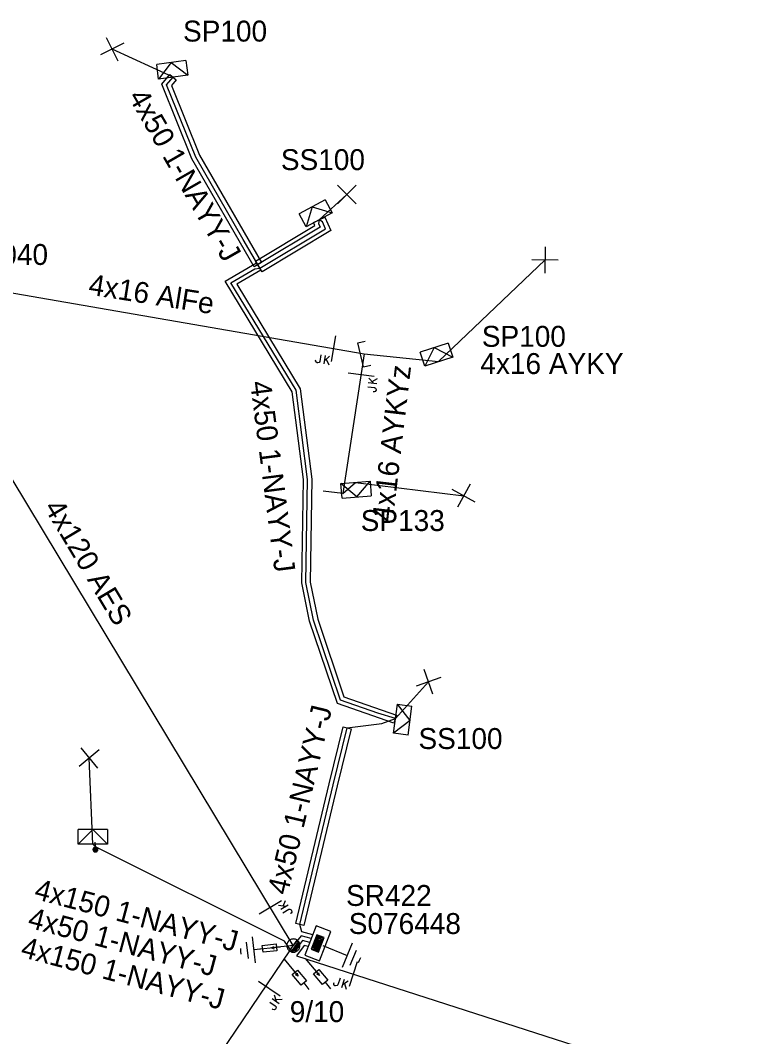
# Model space of a CAD drawing. Extents: x -788458 to -786145, y -1154772 to -1152372.
# Drawn here: x -786394.96 to -786360.56, y -1153494.9 to -1153446.32 of the extents above; entities that cross this region are included whole.
import ezdxf

# ---------------------------------------------------------------- set-up
doc = ezdxf.new("R2010")
doc.units = 0
for name, color, linetype in [('Vrstva 1', 7, 'Continuous'), ('Vrstva 12', 7, 'Continuous'), ('Vrstva 13', 7, 'Continuous'), ('Vrstva 14', 7, 'Continuous'), ('Vrstva 15', 7, 'Continuous'), ('Vrstva 16', 7, 'Continuous'), ('Vrstva 18', 7, 'Continuous'), ('Vrstva 2', 7, 'Continuous'), ('Vrstva 20', 7, 'Continuous'), ('Vrstva 28', 7, 'Continuous'), ('Vrstva 29', 7, 'Continuous'), ('Vrstva 30', 7, 'Continuous'), ('Vrstva 31', 7, 'Continuous'), ('Vrstva 33', 7, 'Continuous'), ('Vrstva 34', 7, 'Continuous'), ('Vrstva 5', 7, 'Continuous'), ('Vrstva 50', 7, 'Continuous'), ('Vrstva 51', 7, 'Continuous'), ('Vrstva 52', 7, 'Continuous'), ('Vrstva 54', 7, 'Continuous'), ('Vrstva 55', 7, 'Continuous'), ('Vrstva 59', 7, 'Continuous'), ('Vrstva 6', 7, 'Continuous'), ('Vrstva 8', 7, 'Continuous'), ('Vrstva 9', 7, 'Continuous')]:
    doc.layers.add(name, color=color, linetype=linetype)

# ---------------------------------------------------------------- blocks, each defined once
blk = doc.blocks.new('NN440')
at = {"layer": 'Vrstva 2'}
for points in [[(0.631, -0.004), (0.627, 0.062), (0.617, 0.127), (0.6, 0.191), (0.577, 0.252), (0.547, 0.311), (0.511, 0.366), (0.469, 0.417), (0.423, 0.464), (0.371, 0.505), (0.316, 0.542), (0.257, 0.571), (0.196, 0.595), (0.132, 0.612), (0.067, 0.622), (0.001, 0.626), (-0.065, 0.622), (-0.13, 0.612), (-0.194, 0.595), (-0.255, 0.571), (-0.314, 0.542), (-0.369, 0.505), (-0.42, 0.464), (-0.467, 0.417), (-0.509, 0.366), (-0.544, 0.311), (-0.574, 0.252), (-0.598, 0.191), (-0.615, 0.127), (-0.626, 0.062), (-0.629, -0.004), (-0.626, -0.07), (-0.615, -0.135), (-0.598, -0.199), (-0.574, -0.26), (-0.544, -0.319), (-0.509, -0.374), (-0.467, -0.426), (-0.42, -0.472), (-0.369, -0.514), (-0.314, -0.55), (-0.255, -0.58), (-0.194, -0.603), (-0.13, -0.62), (-0.065, -0.631), (0.001, -0.634), (0.067, -0.631), (0.132, -0.62), (0.196, -0.603), (0.257, -0.58), (0.316, -0.55), (0.371, -0.514), (0.423, -0.472), (0.469, -0.426), (0.511, -0.374), (0.547, -0.319), (0.577, -0.26), (0.6, -0.199), (0.617, -0.135), (0.627, -0.07), (0.631, -0.004)], [(-0.631, 0), (0.629, 0)], [(-0.601, -0.177), (0.57, -0.177)], [(-0.513, -0.325), (0.501, -0.325)], [(-0.375, -0.473), (0.353, -0.473)]]:
    blk.add_lwpolyline(points, dxfattribs=at)
blk = doc.blocks.new('NN840')
at = {"layer": 'Vrstva 15'}
for points in [[(0.003, 0.619), (0.003, -0.631)], [(-0.538, -0.385), (-0.538, -0.71)], [(-0.332, -0.385), (-0.332, -0.798)], [(-0.332, -0.641), (-0.125, -0.385)], [(-0.745, -0.71), (-0.745, -0.66)], [(-0.73, -0.764), (-0.745, -0.71)], [(-0.657, -0.798), (-0.73, -0.764)], [(-0.627, -0.798), (-0.657, -0.798)], [(-0.558, -0.764), (-0.627, -0.798)], [(-0.538, -0.71), (-0.558, -0.764)], [(-0.263, -0.557), (-0.091, -0.798)]]:
    blk.add_lwpolyline(points, dxfattribs=at)
blk = doc.blocks.new('NN800')
at = {"layer": 'Vrstva 1'}
for points in [[(-0.442, 0.442), (0.442, -0.442)], [(-0.442, -0.442), (0.442, 0.442)]]:
    blk.add_lwpolyline(points, dxfattribs=at)
blk = doc.blocks.new('NN820')
at = {"layer": 'Vrstva 13'}
for points in [[(-0.003, 0.004), (-0.003, -1.049)], [(-0.165, -0.813), (0.165, -0.813)], [(-0.165, -1.473), (-0.165, -0.813)], [(-0.003, -1.049), (-0.062, -0.926)], [(-0.003, -1.049), (0.057, -0.926)], [(0.165, -0.813), (0.165, -1.473)], [(0.165, -1.473), (-0.165, -1.473)], [(-0.003, -1.473), (-0.003, -1.871)]]:
    blk.add_lwpolyline(points, dxfattribs=at)
blk = doc.blocks.new('NN620')
at = {"layer": 'Vrstva 8'}
for points in [[(0.752, 0.004), (-0.748, 0.004)], [(-0.748, 0.004), (-0.748, -0.746)], [(0.752, -0.746), (0.752, 0.004)], [(0.368, -0.18), (-0.376, -0.18)], [(-0.376, -0.18), (-0.376, -0.558)], [(0.321, -0.227), (-0.329, -0.227)], [(-0.329, -0.227), (-0.329, -0.51)], [(0.274, -0.274), (-0.281, -0.274)], [(-0.281, -0.274), (-0.281, -0.463)], [(-0.281, -0.463), (0.274, -0.463)], [(0.227, -0.321), (-0.234, -0.321)], [(-0.234, -0.321), (-0.234, -0.416)], [(-0.234, -0.416), (0.227, -0.416)], [(-0.193, -0.369), (0.185, -0.369)], [(0.227, -0.416), (0.227, -0.321)], [(0.274, -0.463), (0.274, -0.274)], [(0.321, -0.51), (0.321, -0.227)], [(0.368, -0.558), (0.368, -0.18)], [(-0.748, -0.746), (0.752, -0.746)], [(-0.376, -0.558), (0.368, -0.558)], [(-0.329, -0.51), (0.321, -0.51)]]:
    blk.add_lwpolyline(points, dxfattribs=at)
blk = doc.blocks.new('NN630')
at = {"layer": 'Vrstva 9'}
for points in [[(-0.003, -0.7), (-0.703, 0)], [(-0.703, -0.7), (-0.703, 0), (0.697, 0), (0.697, -0.7)], [(-0.003, -0.7), (0.697, 0)], [(-0.703, -0.7), (0.697, -0.7)]]:
    blk.add_lwpolyline(points, dxfattribs=at)
blk = doc.blocks.new('NN810')
at = {"layer": 'Vrstva 14'}
for points in [[(0.004, -0.64), (0.004, -1.89)], [(0.629, -1.89), (-0.621, -1.89)], [(0.388, -2.2), (-0.399, -2.2)], [(0.004, -2.515), (-0.124, -2.515)], [(0.137, -2.515), (0.004, -2.515)]]:
    blk.add_lwpolyline(points, dxfattribs=at)
blk = doc.blocks.new('NN500')
at = {"layer": 'Vrstva 2'}
for points in [[(-0.001, -0.235), (0.023, -0.234), (0.048, -0.23), (0.071, -0.224), (0.094, -0.215), (0.116, -0.204), (0.137, -0.191), (0.156, -0.175), (0.173, -0.158), (0.189, -0.139), (0.202, -0.118), (0.213, -0.096), (0.222, -0.073), (0.229, -0.049), (0.232, -0.025), (0.234, 0), (0.232, 0.024), (0.229, 0.048), (0.222, 0.072), (0.213, 0.095), (0.202, 0.117), (0.189, 0.138), (0.173, 0.157), (0.156, 0.174), (0.137, 0.19), (0.116, 0.203), (0.094, 0.214), (0.071, 0.223), (0.048, 0.229), (0.023, 0.233), (-0.001, 0.235), (-0.026, 0.233), (-0.05, 0.229), (-0.074, 0.223), (-0.097, 0.214), (-0.119, 0.203), (-0.139, 0.19), (-0.158, 0.174), (-0.176, 0.157), (-0.191, 0.138), (-0.205, 0.117), (-0.216, 0.095), (-0.225, 0.072), (-0.231, 0.048), (-0.235, 0.024), (-0.236, 0), (-0.235, -0.025), (-0.231, -0.049), (-0.225, -0.073), (-0.216, -0.096), (-0.205, -0.118), (-0.191, -0.139), (-0.176, -0.158), (-0.158, -0.175), (-0.139, -0.191), (-0.119, -0.204), (-0.097, -0.215), (-0.074, -0.224), (-0.05, -0.23), (-0.026, -0.234), (-0.001, -0.235)], [(-0.001, -0.235), (0.023, -0.234), (0.048, -0.23), (0.071, -0.224), (0.094, -0.215), (0.116, -0.204), (0.137, -0.191), (0.156, -0.175), (0.173, -0.158), (0.189, -0.139), (0.202, -0.118), (0.213, -0.096), (0.222, -0.073), (0.229, -0.049), (0.232, -0.025), (0.234, 0), (0.232, 0.024), (0.229, 0.048), (0.222, 0.072), (0.213, 0.095), (0.202, 0.117), (0.189, 0.138), (0.173, 0.157), (0.156, 0.174), (0.137, 0.19), (0.116, 0.203), (0.094, 0.214), (0.071, 0.223), (0.048, 0.229), (0.023, 0.233), (-0.001, 0.235), (-0.026, 0.233), (-0.05, 0.229), (-0.074, 0.223), (-0.097, 0.214), (-0.119, 0.203), (-0.139, 0.19), (-0.158, 0.174), (-0.176, 0.157), (-0.191, 0.138), (-0.205, 0.117), (-0.216, 0.095), (-0.225, 0.072), (-0.231, 0.048), (-0.235, 0.024), (-0.236, 0), (-0.235, -0.025), (-0.231, -0.049), (-0.225, -0.073), (-0.216, -0.096), (-0.205, -0.118), (-0.191, -0.139), (-0.176, -0.158), (-0.158, -0.175), (-0.139, -0.191), (-0.119, -0.204), (-0.097, -0.215), (-0.074, -0.224), (-0.05, -0.23), (-0.026, -0.234), (-0.001, -0.235)], [(-0.001, -0.206), (0.02, -0.205), (0.041, -0.201), (0.062, -0.196), (0.082, -0.188), (0.101, -0.178), (0.12, -0.167), (0.136, -0.153), (0.151, -0.138), (0.165, -0.121), (0.177, -0.103), (0.186, -0.084), (0.194, -0.064), (0.2, -0.043), (0.203, -0.022), (0.204, 0), (0.203, 0.021), (0.2, 0.042), (0.194, 0.063), (0.186, 0.083), (0.177, 0.102), (0.165, 0.12), (0.151, 0.137), (0.136, 0.152), (0.12, 0.166), (0.101, 0.177), (0.082, 0.187), (0.062, 0.195), (0.041, 0.2), (0.02, 0.204), (-0.001, 0.205), (-0.023, 0.204), (-0.044, 0.2), (-0.065, 0.195), (-0.085, 0.187), (-0.104, 0.177), (-0.122, 0.166), (-0.139, 0.152), (-0.154, 0.137), (-0.167, 0.12), (-0.179, 0.102), (-0.189, 0.083), (-0.197, 0.063), (-0.202, 0.042), (-0.205, 0.021), (-0.207, 0), (-0.205, -0.022), (-0.202, -0.043), (-0.197, -0.064), (-0.189, -0.084), (-0.179, -0.103), (-0.167, -0.121), (-0.154, -0.138), (-0.139, -0.153), (-0.122, -0.167), (-0.104, -0.178), (-0.085, -0.188), (-0.065, -0.196), (-0.044, -0.201), (-0.023, -0.205), (-0.001, -0.206)], [(-0.001, -0.176), (0.017, -0.175), (0.035, -0.172), (0.053, -0.168), (0.07, -0.161), (0.087, -0.153), (0.102, -0.143), (0.116, -0.131), (0.129, -0.118), (0.141, -0.104), (0.151, -0.088), (0.159, -0.072), (0.166, -0.055), (0.171, -0.037), (0.174, -0.019), (0.175, 0), (0.174, 0.018), (0.171, 0.036), (0.166, 0.054), (0.159, 0.071), (0.151, 0.087), (0.141, 0.103), (0.129, 0.117), (0.116, 0.13), (0.102, 0.142), (0.087, 0.152), (0.07, 0.16), (0.053, 0.167), (0.035, 0.172), (0.017, 0.174), (-0.001, 0.175), (-0.02, 0.174), (-0.038, 0.172), (-0.056, 0.167), (-0.073, 0.16), (-0.089, 0.152), (-0.105, 0.142), (-0.119, 0.13), (-0.132, 0.117), (-0.143, 0.103), (-0.153, 0.087), (-0.162, 0.071), (-0.168, 0.054), (-0.173, 0.036), (-0.176, 0.018), (-0.177, 0), (-0.176, -0.019), (-0.173, -0.037), (-0.168, -0.055), (-0.162, -0.072), (-0.153, -0.088), (-0.143, -0.104), (-0.132, -0.118), (-0.119, -0.131), (-0.105, -0.143), (-0.089, -0.153), (-0.073, -0.161), (-0.056, -0.168), (-0.038, -0.172), (-0.02, -0.175), (-0.001, -0.176)], [(-0.001, -0.147), (0.014, -0.146), (0.029, -0.143), (0.044, -0.139), (0.058, -0.134), (0.072, -0.127), (0.085, -0.119), (0.097, -0.109), (0.107, -0.098), (0.117, -0.086), (0.125, -0.073), (0.132, -0.06), (0.138, -0.046), (0.142, -0.031), (0.144, -0.016), (0.145, 0), (0.144, 0.015), (0.142, 0.03), (0.138, 0.045), (0.132, 0.059), (0.125, 0.073), (0.117, 0.086), (0.107, 0.097), (0.097, 0.108), (0.085, 0.118), (0.072, 0.126), (0.058, 0.133), (0.044, 0.139), (0.029, 0.143), (0.014, 0.145), (-0.001, 0.146), (-0.017, 0.145), (-0.032, 0.143), (-0.046, 0.139), (-0.061, 0.133), (-0.074, 0.126), (-0.087, 0.118), (-0.099, 0.108), (-0.11, 0.097), (-0.119, 0.086), (-0.128, 0.073), (-0.135, 0.059), (-0.14, 0.045), (-0.144, 0.03), (-0.147, 0.015), (-0.147, 0), (-0.147, -0.016), (-0.144, -0.031), (-0.14, -0.046), (-0.135, -0.06), (-0.128, -0.073), (-0.119, -0.086), (-0.11, -0.098), (-0.099, -0.109), (-0.087, -0.119), (-0.074, -0.127), (-0.061, -0.134), (-0.046, -0.139), (-0.032, -0.143), (-0.017, -0.146), (-0.001, -0.147)], [(-0.001, -0.117), (0.011, -0.116), (0.023, -0.114), (0.035, -0.111), (0.046, -0.107), (0.057, -0.101), (0.067, -0.095), (0.077, -0.087), (0.085, -0.078), (0.093, -0.069), (0.1, -0.059), (0.105, -0.048), (0.11, -0.036), (0.113, -0.025), (0.115, -0.013), (0.115, 0), (0.115, 0.012), (0.113, 0.024), (0.11, 0.036), (0.105, 0.047), (0.1, 0.058), (0.093, 0.068), (0.085, 0.078), (0.077, 0.086), (0.067, 0.094), (0.057, 0.101), (0.046, 0.106), (0.035, 0.11), (0.023, 0.114), (0.011, 0.116), (-0.001, 0.116), (-0.013, 0.116), (-0.025, 0.114), (-0.037, 0.11), (-0.049, 0.106), (-0.059, 0.101), (-0.07, 0.094), (-0.079, 0.086), (-0.088, 0.078), (-0.096, 0.068), (-0.102, 0.058), (-0.108, 0.047), (-0.112, 0.036), (-0.115, 0.024), (-0.117, 0.012), (-0.118, 0), (-0.117, -0.013), (-0.115, -0.025), (-0.112, -0.036), (-0.108, -0.048), (-0.102, -0.059), (-0.096, -0.069), (-0.088, -0.078), (-0.079, -0.087), (-0.07, -0.095), (-0.059, -0.101), (-0.049, -0.107), (-0.037, -0.111), (-0.025, -0.114), (-0.013, -0.116), (-0.001, -0.117)], [(-0.001, -0.087), (0.008, -0.087), (0.017, -0.085), (0.026, -0.083), (0.034, -0.08), (0.042, -0.076), (0.05, -0.071), (0.057, -0.065), (0.063, -0.059), (0.069, -0.051), (0.074, -0.044), (0.078, -0.036), (0.081, -0.027), (0.084, -0.019), (0.085, -0.01), (0.086, 0), (0.085, 0.009), (0.084, 0.018), (0.081, 0.026), (0.078, 0.035), (0.074, 0.043), (0.069, 0.051), (0.063, 0.058), (0.057, 0.064), (0.05, 0.07), (0.042, 0.075), (0.034, 0.079), (0.026, 0.082), (0.017, 0.085), (0.008, 0.086), (-0.001, 0.087), (-0.01, 0.086), (-0.019, 0.085), (-0.028, 0.082), (-0.037, 0.079), (-0.045, 0.075), (-0.052, 0.07), (-0.059, 0.064), (-0.066, 0.058), (-0.072, 0.051), (-0.077, 0.043), (-0.081, 0.035), (-0.084, 0.026), (-0.086, 0.018), (-0.088, 0.009), (-0.088, 0), (-0.088, -0.01), (-0.086, -0.019), (-0.084, -0.027), (-0.081, -0.036), (-0.077, -0.044), (-0.072, -0.052), (-0.066, -0.059), (-0.059, -0.065), (-0.052, -0.071), (-0.045, -0.076), (-0.037, -0.08), (-0.028, -0.083), (-0.019, -0.085), (-0.01, -0.087), (-0.001, -0.087)], [(-0.001, -0.058), (0.005, -0.057), (0.011, -0.056), (0.016, -0.055), (0.022, -0.053), (0.027, -0.05), (0.032, -0.047), (0.037, -0.043), (0.041, -0.039), (0.045, -0.034), (0.048, -0.029), (0.051, -0.024), (0.053, -0.018), (0.055, -0.012), (0.056, -0.006), (0.056, 0), (0.056, 0.006), (0.055, 0.011), (0.053, 0.017), (0.051, 0.023), (0.048, 0.028), (0.045, 0.033), (0.041, 0.038), (0.037, 0.042), (0.032, 0.046), (0.027, 0.049), (0.022, 0.052), (0.016, 0.054), (0.011, 0.056), (0.005, 0.057), (-0.001, 0.057), (-0.007, 0.057), (-0.013, 0.056), (-0.019, 0.054), (-0.025, 0.052), (-0.03, 0.049), (-0.035, 0.046), (-0.04, 0.042), (-0.044, 0.038), (-0.048, 0.033), (-0.051, 0.028), (-0.054, 0.023), (-0.056, 0.017), (-0.057, 0.011), (-0.058, 0.006), (-0.059, 0), (-0.058, -0.006), (-0.057, -0.012), (-0.056, -0.018), (-0.054, -0.024), (-0.051, -0.029), (-0.048, -0.034), (-0.044, -0.039), (-0.04, -0.043), (-0.035, -0.047), (-0.03, -0.05), (-0.025, -0.053), (-0.019, -0.055), (-0.013, -0.056), (-0.007, -0.057), (-0.001, -0.058)], [(-0.001, -0.028), (0.002, -0.028), (0.005, -0.028), (0.007, -0.027), (0.01, -0.026), (0.013, -0.024), (0.015, -0.023), (0.017, -0.021), (0.019, -0.019), (0.021, -0.017), (0.023, -0.014), (0.024, -0.012), (0.025, -0.009), (0.026, -0.006), (0.026, -0.003), (0.027, 0), (0.026, 0.002), (0.026, 0.005), (0.025, 0.008), (0.024, 0.011), (0.023, 0.013), (0.021, 0.016), (0.019, 0.018), (0.017, 0.02), (0.015, 0.022), (0.013, 0.024), (0.01, 0.025), (0.007, 0.026), (0.005, 0.027), (0.002, 0.027), (-0.001, 0.027), (-0.004, 0.027), (-0.007, 0.027), (-0.01, 0.026), (-0.012, 0.025), (-0.015, 0.024), (-0.018, 0.022), (-0.02, 0.02), (-0.022, 0.018), (-0.024, 0.016), (-0.025, 0.013), (-0.027, 0.011), (-0.028, 0.008), (-0.028, 0.005), (-0.029, 0.002), (-0.029, 0), (-0.029, -0.003), (-0.028, -0.006), (-0.028, -0.009), (-0.027, -0.012), (-0.025, -0.014), (-0.024, -0.017), (-0.022, -0.019), (-0.02, -0.021), (-0.018, -0.023), (-0.015, -0.024), (-0.012, -0.026), (-0.01, -0.027), (-0.007, -0.028), (-0.004, -0.028), (-0.001, -0.028)], [(0.234, 0), (0.704, 0)]]:
    blk.add_lwpolyline(points, dxfattribs=at)
blk = doc.blocks.new('NN510')
at = {"layer": 'Vrstva 2'}
blk.add_lwpolyline([(0.001, 0.002), (0.001, 0.939)], dxfattribs=at)
blk = doc.blocks.new('NN515')
at = {"layer": 'Vrstva 2'}
for points in [[(-0.59, 0.176), (0.591, 0.176)], [(-0.59, 0.176), (-0.59, -0.179)], [(0.591, 0.176), (0.591, -0.179)]]:
    blk.add_lwpolyline(points, dxfattribs=at)

msp = doc.modelspace()

# ---------------------------------------------------------------- linework, layer by layer
at = {"layer": 'Vrstva 1'}
for points in [[(-786401.34, -1153458.3), (-786378.53, -1153462.26)], [(-786392.1, -1153505.61), (-786382.055, -1153490.74)]]:
    msp.add_lwpolyline(points, dxfattribs=at)
at = {"layer": 'Vrstva 20'}
for points in [[(-786387.507, -1153449.158), (-786387.74, -1153449.437), (-786386.4, -1153452.762), (-786383.447, -1153457.894), (-786383.793, -1153458.093), (-786386.76, -1153452.938), (-786388.2, -1153449.363), (-786387.813, -1153448.902)], [(-786380.418, -1153455.724), (-786380.125, -1153456.358), (-786383.415, -1153458.337), (-786383.725, -1153457.823), (-786380.895, -1153456.122), (-786380.962, -1153455.976)], [(-786383.469, -1153458.253), (-786384.624, -1153458.93), (-786381.597, -1153463.933), (-786381.04, -1153468.249), (-786381.12, -1153473.171), (-786380.757, -1153474.938), (-786379.502, -1153478.653), (-786376.994, -1153479.531), (-786377.126, -1153479.909), (-786379.818, -1153478.967), (-786381.143, -1153475.042), (-786381.52, -1153473.209), (-786381.44, -1153468.271), (-786381.983, -1153464.067), (-786385.176, -1153458.79), (-786383.671, -1153457.907)], [(-786379.156, -1153480.178), (-786379.826, -1153482.907), (-786381.415, -1153489.576), (-786381.805, -1153489.484), (-786380.214, -1153482.813), (-786379.544, -1153480.082)]]:
    msp.add_lwpolyline(points, close=True, dxfattribs=at)
at = {"layer": 'Vrstva 5'}
for points in [[(-786377.04, -1153479.69), (-786377.88, -1153479.433), (-786379.66, -1153478.81), (-786380.95, -1153474.99), (-786381.32, -1153473.19), (-786381.24, -1153468.26), (-786381.79, -1153464), (-786384.9, -1153458.86), (-786383.761, -1153458.192), (-786383.518, -1153458.166), (-786380.382, -1153456.279), (-786380.533, -1153455.951), (-786380.69, -1153455.85), (-786380.718, -1153456.029), (-786380.638, -1153456.201), (-786383.622, -1153457.994), (-786384.315, -1153456.785), (-786386.58, -1153452.85), (-786387.97, -1153449.4), (-786387.66, -1153449.03)], [(-786380.989, -1153490.02), (-786381.508, -1153489.881), (-786381.61, -1153489.53), (-786380.02, -1153482.86), (-786379.35, -1153480.13), (-786377.69, -1153479.92), (-786377.04, -1153479.69)], [(-786381.126, -1153490.396), (-786381.474, -1153490.304), (-786381.857, -1153490.811), (-786382.055, -1153490.74)], [(-786381.075, -1153490.203), (-786381.552, -1153490.076), (-786381.92, -1153490.54)], [(-786381.209, -1153490.581), (-786381.395, -1153490.532), (-786381.77, -1153491.026)]]:
    msp.add_lwpolyline(points, dxfattribs=at)
at = {"layer": 'Vrstva 50'}
for points in [[(-786381.92, -1153490.54), (-786401.34, -1153458.3)], [(-786381.77, -1153491.026), (-786354.19, -1153499.92), (-786327.4, -1153511.45), (-786300.99, -1153523.12), (-786278.65, -1153526.63), (-786247.26, -1153533.29)]]:
    msp.add_lwpolyline(points, dxfattribs=at)
at = {"layer": 'Vrstva 52'}
msp.add_lwpolyline([(-786378.53, -1153462.26), (-786374.98, -1153462.63)], dxfattribs=at)
at = {"layer": 'Vrstva 54'}
for points in [[(-786378.53, -1153462.26), (-786379.56, -1153468.93), (-786378.95, -1153468.4)], [(-786382.055, -1153490.74), (-786382.334, -1153490.333), (-786391.34, -1153485.84), (-786391.5, -1153485.69)]]:
    msp.add_lwpolyline(points, dxfattribs=at)
at = {"layer": 'Vrstva 59'}
for points in [[(-786387.66, -1153449.03), (-786390.577, -1153447.69)], [(-786380.69, -1153455.85), (-786379.364, -1153454.638)], [(-786374.98, -1153462.63), (-786369.9, -1153457.77)], [(-786378.95, -1153468.4), (-786373.78, -1153469.04)], [(-786377.04, -1153479.69), (-786375.464, -1153477.937)], [(-786391.5, -1153485.69), (-786391.669, -1153481.578)]]:
    msp.add_lwpolyline(points, dxfattribs=at)

# ---------------------------------------------------------------- block references
at = {"layer": 'Vrstva 13'}
for name, p, rotation in [('NN515', (-786378.53, -1153462.26), 103.15090043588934), ('NN510', (-786379.56, -1153468.93), 83.08525835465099)]:
    msp.add_blockref(name, p, dxfattribs=dict(at, rotation=rotation))
at = {"layer": 'Vrstva 13', "yscale": 0.5}
for name, p, xscale, rotation in [('NN500', (-786391.37, -1153485.95), 0.49999999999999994, 90.95999999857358), ('NN440', (-786381.92, -1153490.54), 0.5, 53.84969451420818)]:
    msp.add_blockref(name, p, dxfattribs=dict(at, xscale=xscale, rotation=rotation))
at = {"layer": 'Vrstva 15'}
for p, rotation in [((-786381.92, -1153490.54), -83.82572397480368), ((-786381.1, -1153490.3), 67.801518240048)]:
    msp.add_blockref('NN810', p, dxfattribs=dict(at, rotation=rotation))
at = {"layer": 'Vrstva 16'}
for p, rotation in [((-786381.92, -1153490.54), -83.78888890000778), ((-786382.357, -1153491.186), 39.403201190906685), ((-786381.345, -1153491.163), 39.75070638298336)]:
    msp.add_blockref('NN820', p, dxfattribs=dict(at, rotation=rotation))
at = {"layer": 'Vrstva 18'}
for p, rotation in [((-786380.009, -1153462.003), -9.022068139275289), ((-786378.683, -1153463.248), 83.27599736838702), ((-786383.022, -1153488.711), 120.8956749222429), ((-786379.06, -1153491.9), -17.873676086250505), ((-786383.067, -1153492.585), 55.975695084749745)]:
    msp.add_blockref('NN840', p, dxfattribs=dict(at, rotation=rotation))
at = {"layer": 'Vrstva 28', "rotation": 68.64901972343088}
msp.add_blockref('NN620', (-786381.1, -1153490.3), dxfattribs=at)
at = {"layer": 'Vrstva 31'}
for p, rotation in [((-786387.66, -1153449.03), -172.42704490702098), ((-786380.69, -1153455.85), -151.5643909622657), ((-786374.98, -1153462.63), -162.3902420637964), ((-786378.95, -1153468.4), 4.8207661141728), ((-786377.04, -1153479.69), 82.32636075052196), ((-786391.5, -1153485.69), 180)]:
    msp.add_blockref('NN630', p, dxfattribs=dict(at, rotation=rotation))
at = {"layer": 'Vrstva 34'}
for p, rotation in [((-786390.577, -1153447.69), -108.34627494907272), ((-786369.9, -1153457.77), -136.17543062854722), ((-786373.78, -1153469.04), -163.94491390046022), ((-786375.464, -1153477.937), 154.2612611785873), ((-786391.669, -1153481.578), -95.47917221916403)]:
    msp.add_blockref('NN800', p, dxfattribs=dict(at, rotation=rotation))
msp.add_blockref('NN800', (-786379.364, -1153454.638), dxfattribs=at)

# ---------------------------------------------------------------- texts
at = {"layer": 'Vrstva 12'}
msp.add_text('9/10', height=1, dxfattribs=at).set_placement((-786382.09, -1153494.197))
at = {"layer": 'Vrstva 2'}
msp.add_text('4x16 AlFe', height=1, rotation=350.978, dxfattribs=at).set_placement((-786391.742, -1153459.418))
at = {"layer": 'Vrstva 29'}
for s, p in [('S027040', (-786398.988, -1153458.008)), ('S076448', (-786379.271, -1153489.988))]:
    msp.add_text(s, height=1, dxfattribs=at).set_placement(p)
at = {"layer": 'Vrstva 30'}
msp.add_text('SR422', height=1, dxfattribs=at).set_placement((-786379.402, -1153488.646))
at = {"layer": 'Vrstva 33'}
for s, p in [('SP100', (-786387.187, -1153447.331)), ('SS100', (-786382.515, -1153453.475)), ('SP100', (-786372.918, -1153461.921)), ('SP133', (-786378.702, -1153470.725)), ('SS100', (-786375.943, -1153481.145))]:
    msp.add_text(s, height=1, dxfattribs=at).set_placement(p)
at = {"layer": 'Vrstva 51'}
msp.add_text('4x120 AES', height=1, rotation=300.896, dxfattribs=at).set_placement((-786393.854, -1153469.599))
at = {"layer": 'Vrstva 54'}
msp.add_text('4x16 AYKY', height=1, dxfattribs=at).set_placement((-786372.988, -1153463.222))
at = {"layer": 'Vrstva 55'}
msp.add_text('4x16 AYKYz', height=1, rotation=83.276, dxfattribs=at).set_placement((-786377.171, -1153470.307))
at = {"layer": 'Vrstva 6'}
for s, rotation, p in [('4x50 1-NAYY-J', 299.922, (-786389.828, -1153449.962)), ('4x50 1-NAYY-J', 277.357, (-786383.987, -1153463.609)), ('4x50 1-NAYY-J', 76.592, (-786382.197, -1153488.166)), ('4x150 1-NAYY-J', 345.136, (-786394.343, -1153488.293)), ('4x50 1-NAYY-J', 345.136, (-786394.654, -1153489.666)), ('4x150 1-NAYY-J', 345.136, (-786394.992, -1153491.066))]:
    msp.add_text(s, height=1, rotation=rotation, dxfattribs=at).set_placement(p)

doc.saveas('drawing.dxf')
